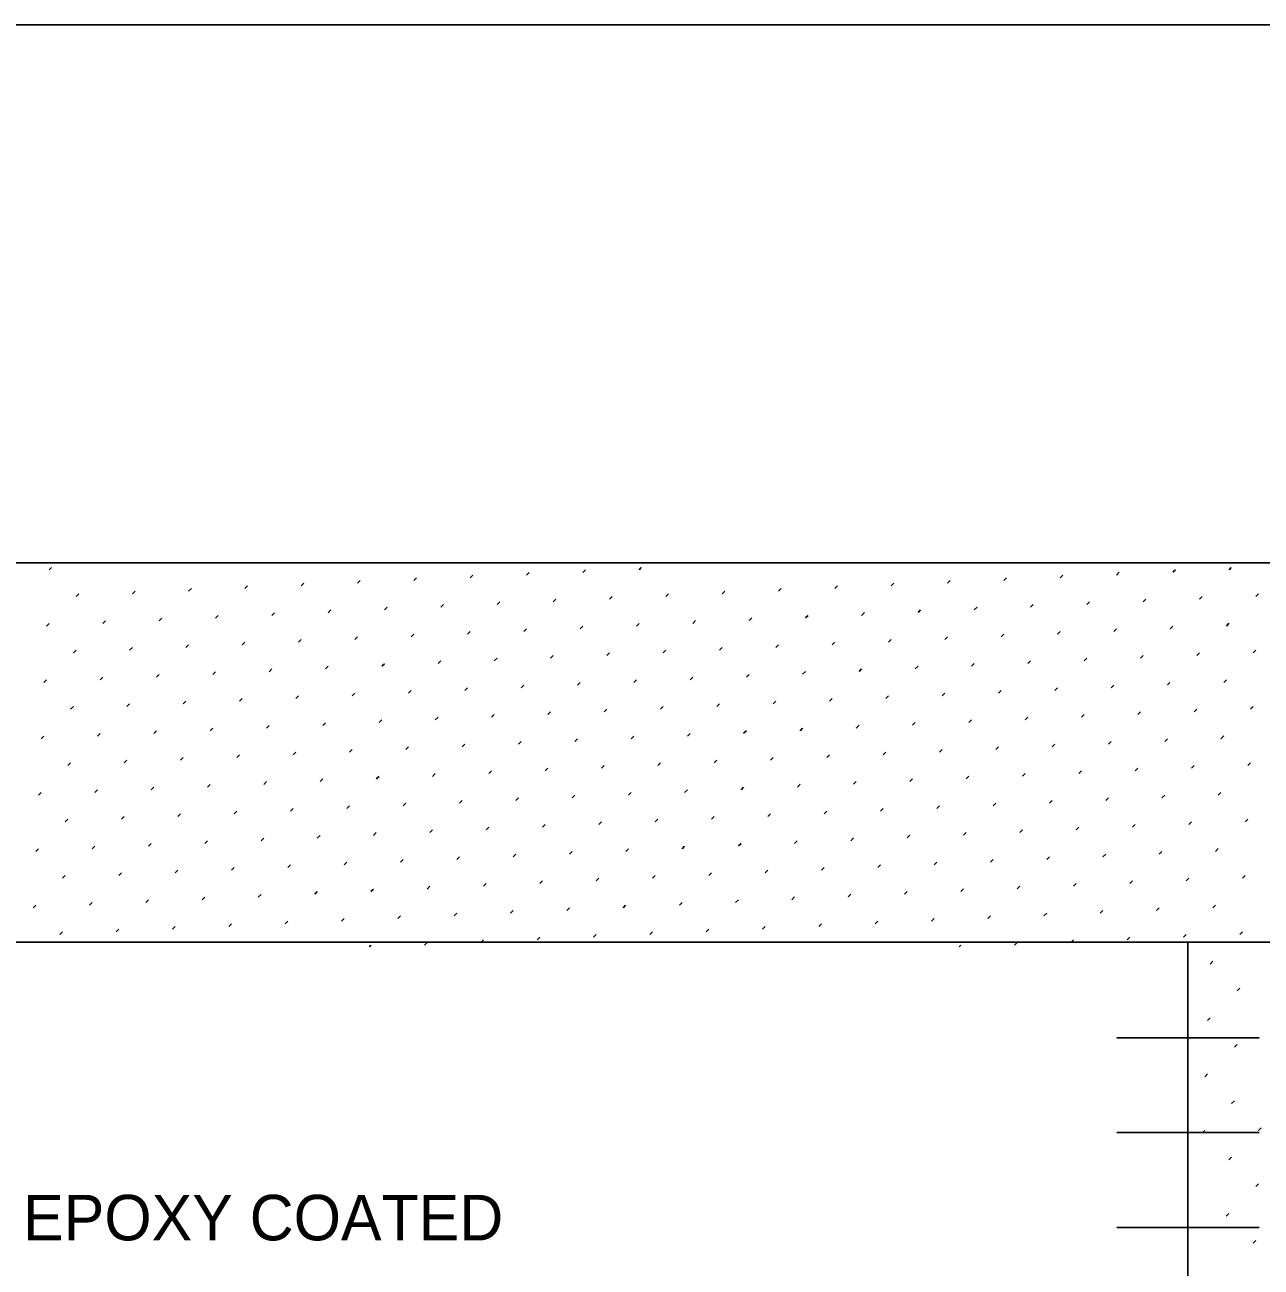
# Model space of a CAD drawing. Extents: x 49991.4 to 50021, y 49987.6 to 50011.4.
# Drawn here: x 50004.526 to 50006.156, y 49997.362 to 49998.999 of the extents above; entities that cross this region are included whole.
import ezdxf

# ---------------------------------------------------------------- set-up
doc = ezdxf.new("R2010")
doc.units = 0
for name, color, linetype in [('Level 1', 7, 'Continuous'), ('Level 10', 7, 'Continuous'), ('Level 2', 7, 'Continuous'), ('Level 4', 7, 'Continuous')]:
    doc.layers.add(name, color=color, linetype=linetype)

msp = doc.modelspace()

# ---------------------------------------------------------------- linework, layer by layer
at = {"layer": 'Level 1'}
for p, q in [((50015.1301, 49998.2903), (50001.3364, 49998.2903)), ((50004.1848, 49997.7903), (50006.0598, 49997.7903)), ((50006.0598, 49994.7903), (50006.0598, 49997.7903)), ((50006.0598, 49997.7903), (50007.9348, 49997.7903))]:
    msp.add_line(p, q, dxfattribs=at)
msp.add_lwpolyline([(49999.3835, 49998.9992), (50016.7501, 49998.9992), (50016.7501, 49987.7988), (49999.3835, 49987.7988)], close=True, dxfattribs=at)
at = {"layer": 'Level 10'}
for p, q in [((50004.5582, 49998.281), (50004.561, 49998.2838)), ((50005.3361, 49998.281), (50005.3389, 49998.2838)), ((50006.114, 49998.2811), (50006.1167, 49998.2838)), ((50005.0391, 49998.2669), (50005.0426, 49998.2704)), ((50005.1133, 49998.2704), (50005.1168, 49998.2739)), ((50005.1876, 49998.2739), (50005.1911, 49998.2775)), ((50005.2618, 49998.2775), (50005.2653, 49998.281)), ((50005.8169, 49998.2669), (50005.8205, 49998.2705)), ((50005.8912, 49998.2705), (50005.8947, 49998.274)), ((50005.9654, 49998.274), (50005.969, 49998.2776)), ((50006.0397, 49998.2776), (50006.0432, 49998.2811)), ((50004.6678, 49998.2491), (50004.6713, 49998.2527)), ((50004.742, 49998.2527), (50004.7456, 49998.2562)), ((50004.8163, 49998.2562), (50004.8198, 49998.2598)), ((50004.8905, 49998.2598), (50004.8941, 49998.2633)), ((50004.9648, 49998.2633), (50004.9683, 49998.2669)), ((50005.4457, 49998.2492), (50005.4492, 49998.2528)), ((50005.5199, 49998.2528), (50005.5235, 49998.2563)), ((50005.5942, 49998.2563), (50005.5977, 49998.2598)), ((50005.6684, 49998.2598), (50005.672, 49998.2634)), ((50005.7427, 49998.2634), (50005.7462, 49998.2669)), ((50004.5935, 49998.2456), (50004.5971, 49998.2491)), ((50005.0744, 49998.2315), (50005.0779, 49998.235)), ((50005.1487, 49998.235), (50005.1522, 49998.2386)), ((50005.2229, 49998.2386), (50005.2264, 49998.2421)), ((50005.2972, 49998.2421), (50005.3007, 49998.2457)), ((50005.3714, 49998.2457), (50005.375, 49998.2492)), ((50005.8523, 49998.2316), (50005.8558, 49998.2351)), ((50005.9265, 49998.2351), (50005.9301, 49998.2387)), ((50006.0008, 49998.2387), (50006.0043, 49998.2422)), ((50006.0751, 49998.2422), (50006.0786, 49998.2457)), ((50006.1493, 49998.2457), (50006.1528, 49998.2493)), ((50004.7774, 49998.2173), (50004.7809, 49998.2209)), ((50004.8516, 49998.2209), (50004.8552, 49998.2244)), ((50004.9259, 49998.2244), (50004.9294, 49998.228)), ((50005.0002, 49998.228), (50005.0037, 49998.2315)), ((50005.5553, 49998.2174), (50005.5588, 49998.2209)), ((50005.6295, 49998.2209), (50005.6331, 49998.2245)), ((50005.7038, 49998.2245), (50005.7073, 49998.228)), ((50005.778, 49998.228), (50005.7816, 49998.2316)), ((50004.5546, 49998.2067), (50004.5582, 49998.2102)), ((50004.6289, 49998.2102), (50004.6324, 49998.2138)), ((50004.7031, 49998.2138), (50004.7067, 49998.2173)), ((50005.184, 49998.1997), (50005.1876, 49998.2032)), ((50005.2583, 49998.2032), (50005.2618, 49998.2068)), ((50005.3325, 49998.2068), (50005.3361, 49998.2103)), ((50005.4068, 49998.2103), (50005.4103, 49998.2139)), ((50005.481, 49998.2139), (50005.4846, 49998.2174)), ((50005.9619, 49998.1998), (50005.9654, 49998.2033)), ((50006.0362, 49998.2033), (50006.0397, 49998.2068)), ((50006.1104, 49998.2068), (50006.1139, 49998.2104)), ((50004.8127, 49998.182), (50004.8163, 49998.1855)), ((50004.887, 49998.1855), (50004.8905, 49998.1891)), ((50004.9613, 49998.1891), (50004.9648, 49998.1926)), ((50005.0355, 49998.1926), (50005.039, 49998.1961)), ((50005.1098, 49998.1962), (50005.1133, 49998.1997)), ((50005.5906, 49998.1821), (50005.5942, 49998.1856)), ((50005.6649, 49998.1856), (50005.6684, 49998.1891)), ((50005.7391, 49998.1891), (50005.7427, 49998.1927)), ((50005.8134, 49998.1927), (50005.8169, 49998.1962)), ((50005.8876, 49998.1962), (50005.8912, 49998.1998)), ((50004.59, 49998.1714), (50004.5935, 49998.1749)), ((50004.6642, 49998.1749), (50004.6678, 49998.1784)), ((50004.7385, 49998.1784), (50004.742, 49998.182)), ((50005.2936, 49998.1679), (50005.2972, 49998.1714)), ((50005.3679, 49998.1714), (50005.3714, 49998.175)), ((50005.4421, 49998.175), (50005.4457, 49998.1785)), ((50005.5164, 49998.1785), (50005.5199, 49998.182)), ((50006.0715, 49998.168), (50006.075, 49998.1715)), ((50006.1458, 49998.1715), (50006.1493, 49998.175)), ((50004.9224, 49998.1502), (50004.9259, 49998.1537)), ((50004.9966, 49998.1537), (50005.0001, 49998.1572)), ((50005.0709, 49998.1573), (50005.0744, 49998.1608)), ((50005.1451, 49998.1608), (50005.1487, 49998.1643)), ((50005.2194, 49998.1643), (50005.2229, 49998.1679)), ((50005.7002, 49998.1502), (50005.7038, 49998.1538)), ((50005.7745, 49998.1538), (50005.778, 49998.1573)), ((50005.8488, 49998.1573), (50005.8523, 49998.1609)), ((50005.923, 49998.1609), (50005.9265, 49998.1644)), ((50005.9973, 49998.1644), (50006.0008, 49998.1679)), ((50004.6253, 49998.136), (50004.6289, 49998.1395)), ((50004.6996, 49998.1395), (50004.7031, 49998.1431)), ((50004.7739, 49998.1431), (50004.7774, 49998.1466)), ((50004.8481, 49998.1466), (50004.8516, 49998.1502)), ((50005.329, 49998.1325), (50005.3325, 49998.1361)), ((50005.4032, 49998.1361), (50005.4068, 49998.1396)), ((50005.4775, 49998.1396), (50005.481, 49998.1431)), ((50005.5517, 49998.1432), (50005.5553, 49998.1467)), ((50005.626, 49998.1467), (50005.6295, 49998.1502)), ((50006.1069, 49998.1326), (50006.1104, 49998.1361)), ((50004.5511, 49998.1325), (50004.5546, 49998.136)), ((50005.032, 49998.1184), (50005.0355, 49998.1219)), ((50005.1062, 49998.1219), (50005.1098, 49998.1254)), ((50005.1805, 49998.1254), (50005.184, 49998.129)), ((50005.2547, 49998.129), (50005.2583, 49998.1325)), ((50005.8099, 49998.1184), (50005.8134, 49998.122)), ((50005.8841, 49998.122), (50005.8876, 49998.1255)), ((50005.9584, 49998.1255), (50005.9619, 49998.129)), ((50006.0326, 49998.1291), (50006.0361, 49998.1326)), ((50004.6607, 49998.1006), (50004.6642, 49998.1042)), ((50004.735, 49998.1042), (50004.7385, 49998.1077)), ((50004.8092, 49998.1077), (50004.8127, 49998.1113)), ((50004.8835, 49998.1113), (50004.887, 49998.1148)), ((50004.9577, 49998.1148), (50004.9612, 49998.1183)), ((50005.4386, 49998.1007), (50005.4421, 49998.1042)), ((50005.5128, 49998.1043), (50005.5164, 49998.1078)), ((50005.5871, 49998.1078), (50005.5906, 49998.1113)), ((50005.6613, 49998.1113), (50005.6649, 49998.1149)), ((50005.7356, 49998.1149), (50005.7391, 49998.1184)), ((50004.5864, 49998.0971), (50004.59, 49998.1006)), ((50005.1416, 49998.0865), (50005.1451, 49998.0901)), ((50005.2158, 49998.0901), (50005.2194, 49998.0936)), ((50005.2901, 49998.0936), (50005.2936, 49998.0972)), ((50005.3643, 49998.0972), (50005.3679, 49998.1007)), ((50005.9195, 49998.0866), (50005.923, 49998.0901)), ((50005.9937, 49998.0902), (50005.9973, 49998.0937)), ((50006.068, 49998.0937), (50006.0715, 49998.0972)), ((50006.1422, 49998.0972), (50006.1458, 49998.1008)), ((50004.7703, 49998.0688), (50004.7738, 49998.0724)), ((50004.8446, 49998.0724), (50004.8481, 49998.0759)), ((50004.9188, 49998.0759), (50004.9224, 49998.0794)), ((50004.9931, 49998.0795), (50004.9966, 49998.083)), ((50005.0673, 49998.083), (50005.0709, 49998.0865)), ((50005.5482, 49998.0689), (50005.5517, 49998.0724)), ((50005.6224, 49998.0724), (50005.626, 49998.076)), ((50005.6967, 49998.076), (50005.7002, 49998.0795)), ((50005.771, 49998.0795), (50005.7745, 49998.0831)), ((50005.8452, 49998.0831), (50005.8487, 49998.0866)), ((50004.5475, 49998.0582), (50004.5511, 49998.0617)), ((50004.6218, 49998.0617), (50004.6253, 49998.0653)), ((50004.6961, 49998.0653), (50004.6996, 49998.0688)), ((50005.1769, 49998.0512), (50005.1805, 49998.0547)), ((50005.2512, 49998.0547), (50005.2547, 49998.0583)), ((50005.3254, 49998.0583), (50005.329, 49998.0618)), ((50005.3997, 49998.0618), (50005.4032, 49998.0653)), ((50005.4739, 49998.0654), (50005.4775, 49998.0689)), ((50005.9548, 49998.0513), (50005.9584, 49998.0548)), ((50006.0291, 49998.0548), (50006.0326, 49998.0583)), ((50006.1033, 49998.0583), (50006.1069, 49998.0619)), ((50004.8799, 49998.037), (50004.8835, 49998.0406)), ((50004.9542, 49998.0406), (50004.9577, 49998.0441)), ((50005.0284, 49998.0441), (50005.032, 49998.0476)), ((50005.1027, 49998.0476), (50005.1062, 49998.0512)), ((50005.6578, 49998.0371), (50005.6613, 49998.0406)), ((50005.7321, 49998.0406), (50005.7356, 49998.0442)), ((50005.8063, 49998.0442), (50005.8098, 49998.0477)), ((50005.8806, 49998.0477), (50005.8841, 49998.0512)), ((50004.5829, 49998.0228), (50004.5864, 49998.0264)), ((50004.6572, 49998.0264), (50004.6607, 49998.0299)), ((50004.7314, 49998.0299), (50004.7349, 49998.0335)), ((50004.8057, 49998.0335), (50004.8092, 49998.037)), ((50005.2865, 49998.0194), (50005.2901, 49998.0229)), ((50005.3608, 49998.0229), (50005.3643, 49998.0265)), ((50005.435, 49998.0265), (50005.4386, 49998.03)), ((50005.5093, 49998.03), (50005.5128, 49998.0335)), ((50005.5836, 49998.0335), (50005.5871, 49998.0371)), ((50006.0644, 49998.0194), (50006.068, 49998.023)), ((50006.1387, 49998.023), (50006.1422, 49998.0265)), ((50004.9153, 49998.0017), (50004.9188, 49998.0052)), ((50004.9895, 49998.0052), (50004.9931, 49998.0087)), ((50005.0638, 49998.0087), (50005.0673, 49998.0123)), ((50005.138, 49998.0123), (50005.1416, 49998.0158)), ((50005.2123, 49998.0158), (50005.2158, 49998.0194)), ((50005.6932, 49998.0017), (50005.6967, 49998.0053)), ((50005.7674, 49998.0053), (50005.7709, 49998.0088)), ((50005.8417, 49998.0088), (50005.8452, 49998.0124)), ((50005.9159, 49998.0124), (50005.9195, 49998.0159)), ((50005.9902, 49998.0159), (50005.9937, 49998.0194)), ((50004.6183, 49997.9875), (50004.6218, 49997.991)), ((50004.6925, 49997.991), (50004.696, 49997.9946)), ((50004.7668, 49997.9946), (50004.7703, 49997.9981)), ((50004.841, 49997.9981), (50004.8446, 49998.0017)), ((50005.3961, 49997.9876), (50005.3997, 49997.9911)), ((50005.4704, 49997.9911), (50005.4739, 49997.9946)), ((50005.5447, 49997.9946), (50005.5482, 49997.9982)), ((50005.6189, 49997.9982), (50005.6224, 49998.0017)), ((50004.544, 49997.9839), (50004.5475, 49997.9875)), ((50005.0249, 49997.9698), (50005.0284, 49997.9734)), ((50005.0991, 49997.9734), (50005.1027, 49997.9769)), ((50005.1734, 49997.9769), (50005.1769, 49997.9805)), ((50005.2476, 49997.9805), (50005.2512, 49997.984)), ((50005.3219, 49997.984), (50005.3254, 49997.9876)), ((50005.8028, 49997.9699), (50005.8063, 49997.9735)), ((50005.877, 49997.9735), (50005.8806, 49997.977)), ((50005.9513, 49997.977), (50005.9548, 49997.9805)), ((50006.0255, 49997.9805), (50006.0291, 49997.9841)), ((50006.0998, 49997.9841), (50006.1033, 49997.9876)), ((50004.7279, 49997.9557), (50004.7314, 49997.9592)), ((50004.8021, 49997.9592), (50004.8057, 49997.9628)), ((50004.8764, 49997.9628), (50004.8799, 49997.9663)), ((50004.9506, 49997.9663), (50004.9542, 49997.9698)), ((50005.5058, 49997.9557), (50005.5093, 49997.9593)), ((50005.58, 49997.9593), (50005.5835, 49997.9628)), ((50005.6543, 49997.9628), (50005.6578, 49997.9664)), ((50005.7285, 49997.9664), (50005.7321, 49997.9699)), ((50004.5794, 49997.9486), (50004.5829, 49997.9521)), ((50004.6536, 49997.9521), (50004.6571, 49997.9557)), ((50005.1345, 49997.938), (50005.138, 49997.9416)), ((50005.2087, 49997.9416), (50005.2123, 49997.9451)), ((50005.283, 49997.9451), (50005.2865, 49997.9487)), ((50005.3572, 49997.9487), (50005.3608, 49997.9522)), ((50005.4315, 49997.9522), (50005.435, 49997.9557)), ((50005.9124, 49997.9381), (50005.9159, 49997.9416)), ((50005.9866, 49997.9416), (50005.9902, 49997.9452)), ((50006.0609, 49997.9452), (50006.0644, 49997.9487)), ((50006.1351, 49997.9487), (50006.1387, 49997.9523)), ((50004.7632, 49997.9203), (50004.7668, 49997.9239)), ((50004.8375, 49997.9239), (50004.841, 49997.9274)), ((50004.9117, 49997.9274), (50004.9153, 49997.9309)), ((50004.986, 49997.9309), (50004.9895, 49997.9345)), ((50005.0602, 49997.9345), (50005.0638, 49997.938)), ((50005.5411, 49997.9204), (50005.5446, 49997.9239)), ((50005.6154, 49997.9239), (50005.6189, 49997.9275)), ((50005.6896, 49997.9275), (50005.6932, 49997.931)), ((50005.7639, 49997.931), (50005.7674, 49997.9346)), ((50005.8381, 49997.9346), (50005.8417, 49997.9381)), ((50004.5405, 49997.9097), (50004.544, 49997.9132)), ((50004.6147, 49997.9132), (50004.6183, 49997.9168)), ((50004.689, 49997.9168), (50004.6925, 49997.9203)), ((50005.2441, 49997.9062), (50005.2476, 49997.9098)), ((50005.3184, 49997.9098), (50005.3219, 49997.9133)), ((50005.3926, 49997.9133), (50005.3961, 49997.9168)), ((50005.4669, 49997.9169), (50005.4704, 49997.9204)), ((50006.022, 49997.9063), (50006.0255, 49997.9098)), ((50006.0962, 49997.9098), (50006.0998, 49997.9134)), ((50004.8728, 49997.8885), (50004.8764, 49997.892)), ((50004.9471, 49997.8921), (50004.9506, 49997.8956)), ((50005.0213, 49997.8956), (50005.0249, 49997.8991)), ((50005.0956, 49997.8991), (50005.0991, 49997.9027)), ((50005.1698, 49997.9027), (50005.1734, 49997.9062)), ((50005.6507, 49997.8886), (50005.6543, 49997.8921)), ((50005.725, 49997.8921), (50005.7285, 49997.8957)), ((50005.7992, 49997.8957), (50005.8028, 49997.8992)), ((50005.8735, 49997.8992), (50005.877, 49997.9027)), ((50005.9477, 49997.9028), (50005.9513, 49997.9063)), ((50004.5758, 49997.8743), (50004.5794, 49997.8779)), ((50004.6501, 49997.8779), (50004.6536, 49997.8814)), ((50004.7243, 49997.8814), (50004.7279, 49997.885)), ((50004.7986, 49997.885), (50004.8021, 49997.8885)), ((50005.2795, 49997.8709), (50005.283, 49997.8744)), ((50005.3537, 49997.8744), (50005.3572, 49997.8779)), ((50005.428, 49997.878), (50005.4315, 49997.8815)), ((50005.5022, 49997.8815), (50005.5057, 49997.885)), ((50005.5765, 49997.885), (50005.58, 49997.8886)), ((50006.0573, 49997.8709), (50006.0609, 49997.8745)), ((50006.1316, 49997.8745), (50006.1351, 49997.878)), ((50004.9824, 49997.8567), (50004.986, 49997.8602)), ((50005.0567, 49997.8602), (50005.0602, 49997.8638)), ((50005.1309, 49997.8638), (50005.1345, 49997.8673)), ((50005.2052, 49997.8673), (50005.2087, 49997.8709)), ((50005.7603, 49997.8568), (50005.7639, 49997.8603)), ((50005.8346, 49997.8603), (50005.8381, 49997.8638)), ((50005.9088, 49997.8639), (50005.9124, 49997.8674)), ((50005.9831, 49997.8674), (50005.9866, 49997.8709)), ((50004.6112, 49997.839), (50004.6147, 49997.8425)), ((50004.6854, 49997.8425), (50004.689, 49997.8461)), ((50004.7597, 49997.8461), (50004.7632, 49997.8496)), ((50004.8339, 49997.8496), (50004.8375, 49997.8531)), ((50004.9082, 49997.8532), (50004.9117, 49997.8567)), ((50005.3891, 49997.8391), (50005.3926, 49997.8426)), ((50005.4633, 49997.8426), (50005.4669, 49997.8461)), ((50005.5376, 49997.8461), (50005.5411, 49997.8497)), ((50005.6118, 49997.8497), (50005.6154, 49997.8532)), ((50005.6861, 49997.8532), (50005.6896, 49997.8568)), ((50004.5369, 49997.8354), (50004.5405, 49997.839)), ((50005.092, 49997.8249), (50005.0956, 49997.8284)), ((50005.1663, 49997.8284), (50005.1698, 49997.832)), ((50005.2406, 49997.832), (50005.2441, 49997.8355)), ((50005.3148, 49997.8355), (50005.3183, 49997.839)), ((50005.8699, 49997.825), (50005.8735, 49997.8285)), ((50005.9442, 49997.8285), (50005.9477, 49997.832)), ((50006.0184, 49997.832), (50006.022, 49997.8356)), ((50006.0927, 49997.8356), (50006.0962, 49997.8391)), ((50004.7208, 49997.8072), (50004.7243, 49997.8107)), ((50004.795, 49997.8107), (50004.7986, 49997.8142)), ((50004.8693, 49997.8143), (50004.8728, 49997.8178)), ((50004.9435, 49997.8178), (50004.9471, 49997.8213)), ((50005.0178, 49997.8213), (50005.0213, 49997.8249)), ((50005.4987, 49997.8072), (50005.5022, 49997.8108)), ((50005.5729, 49997.8108), (50005.5765, 49997.8143)), ((50005.6472, 49997.8143), (50005.6507, 49997.8179)), ((50005.7214, 49997.8179), (50005.725, 49997.8214)), ((50005.7957, 49997.8214), (50005.7992, 49997.8249)), ((50004.5723, 49997.8001), (50004.5758, 49997.8036)), ((50004.6465, 49997.8036), (50004.6501, 49997.8072)), ((50005.1274, 49997.7895), (50005.1309, 49997.7931)), ((50005.2017, 49997.7931), (50005.2052, 49997.7966)), ((50005.2759, 49997.7966), (50005.2794, 49997.8001)), ((50005.3502, 49997.8002), (50005.3537, 49997.8037)), ((50005.4244, 49997.8037), (50005.428, 49997.8072)), ((50005.9053, 49997.7896), (50005.9088, 49997.7931)), ((50005.9795, 49997.7931), (50005.9831, 49997.7967)), ((50006.0538, 49997.7967), (50006.0573, 49997.8002)), ((50006.1281, 49997.8002), (50006.1316, 49997.8038)), ((50004.9803, 49997.7838), (50004.9824, 49997.786)), ((50005.0532, 49997.786), (50005.0567, 49997.7895)), ((50005.7581, 49997.7838), (50005.7603, 49997.786)), ((50005.831, 49997.7861), (50005.8346, 49997.7896)), ((50006.0892, 49997.7613), (50006.0927, 49997.7649)), ((50006.1245, 49997.726), (50006.128, 49997.7295)), ((50006.0856, 49997.6871), (50006.0891, 49997.6906)), ((50006.121, 49997.6517), (50006.1245, 49997.6553)), ((50006.0821, 49997.6128), (50006.0856, 49997.6164)), ((50006.1174, 49997.5775), (50006.121, 49997.581)), ((50006.0788, 49997.5388), (50006.0821, 49997.5421)), ((50006.1528, 49997.5421), (50006.1563, 49997.5456)), ((50006.1139, 49997.5032), (50006.1174, 49997.5067)), ((50006.1492, 49997.4679), (50006.1528, 49997.4714)), ((50006.1103, 49997.429), (50006.1139, 49997.4325)), ((50006.1457, 49997.3936), (50006.1492, 49997.3971))]:
    msp.add_line(p, q, dxfattribs=at)
at = {"layer": 'Level 4'}
for p, q in [((50005.966, 49997.6642), (50006.1535, 49997.6642)), ((50005.966, 49997.5392), (50006.1535, 49997.5392)), ((50005.966, 49997.4142), (50006.1535, 49997.4142))]:
    msp.add_line(p, q, dxfattribs=at)

# ---------------------------------------------------------------- texts
at = {"layer": 'Level 2'}
msp.add_text('EPOXY COATED', height=0.06, dxfattribs=at).set_placement((50004.5238, 49997.3971))

doc.saveas('drawing.dxf')
